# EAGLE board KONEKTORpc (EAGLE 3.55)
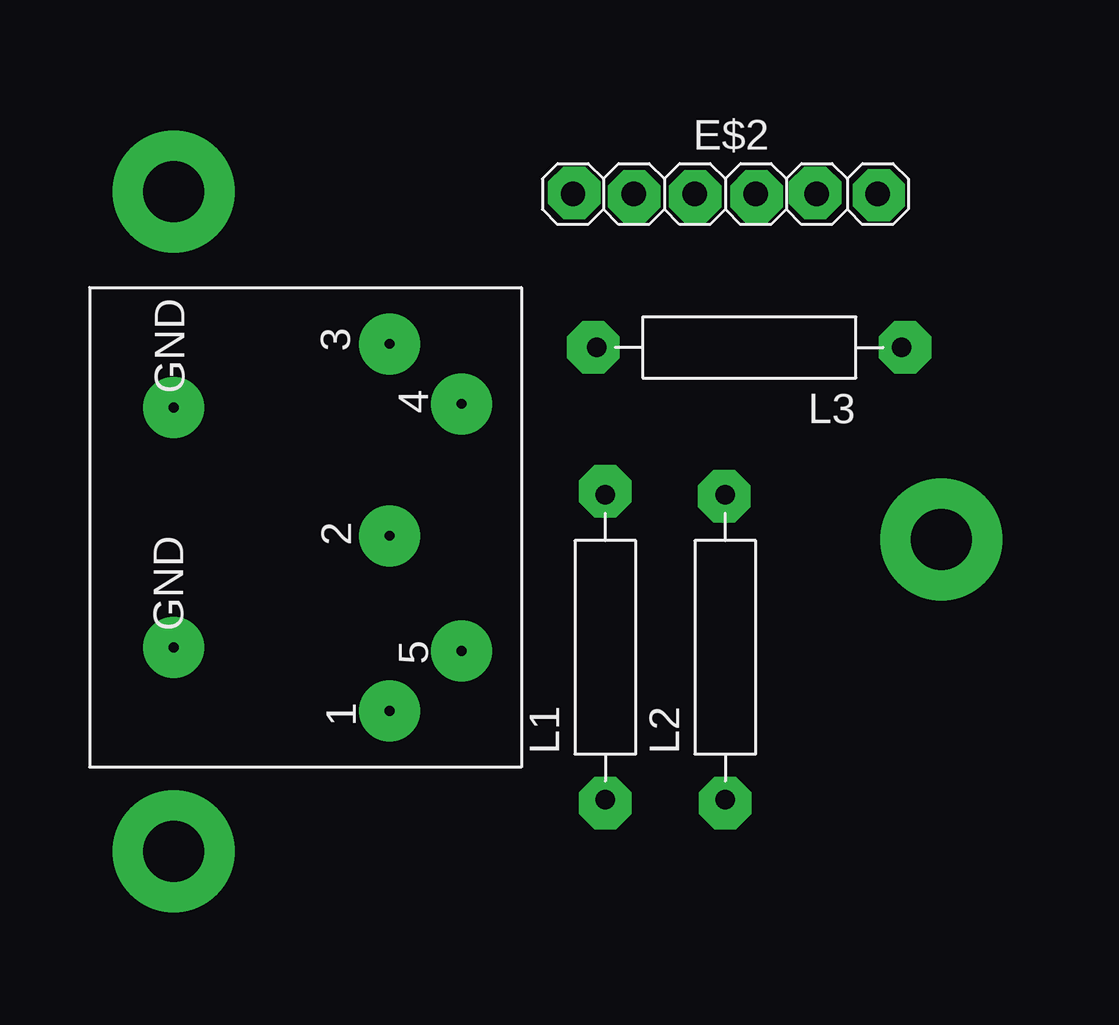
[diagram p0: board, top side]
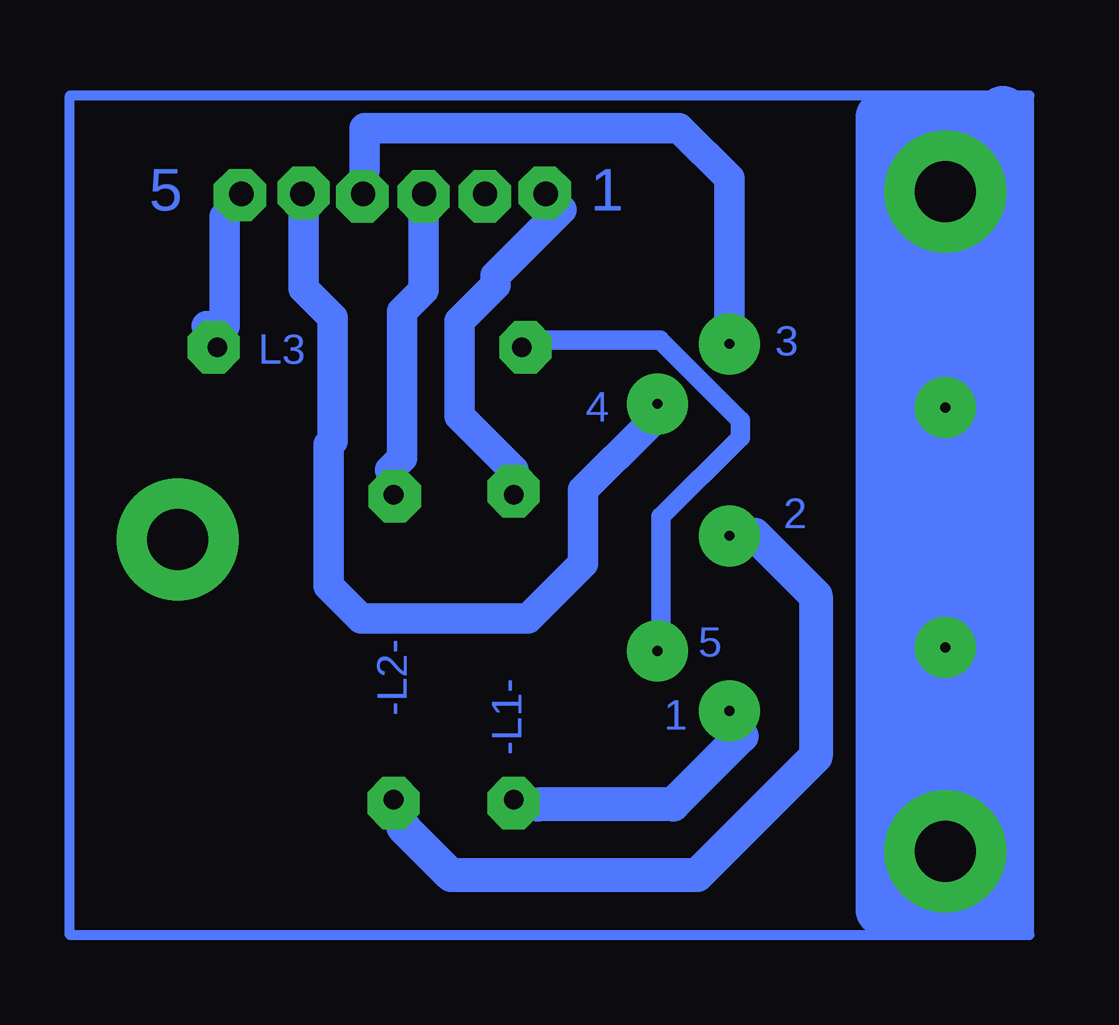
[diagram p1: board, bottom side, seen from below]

No outline drawn. Coordinates in mm, seen from the top.
Copper layers used: Bottom

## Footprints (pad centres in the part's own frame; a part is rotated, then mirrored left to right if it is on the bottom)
N 5 C = drill 0.406 pad 2.54 round:  5,3.5;  15,3.5;  10.35,12.5;  2.35,12.5;  17.65,12.5;  15.15,15.5;  4.85,15.5
06 = drill 1.016 pad 1.575 octagon:  -6.35,0;  -3.81,0;  -1.27,0;  1.27,0;  3.81,0;  6.35,0
12,5 = drill 0.813 pad 1.397 octagon:  -6.35,0;  6.35,0

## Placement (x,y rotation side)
E$1  [N 5 C]  0,27 270 top
E$2  K1  [06]  26.5,30.9 0 top
L1  [12,5]  21.5,12 90 top
L2  [12,5]  26.5,12 90 top
L3  [12,5]  27.5,24.5 180 top

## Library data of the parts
E$1 = hacesoft
E$2 = PINHEAD
L1-L3 = PASSIVE

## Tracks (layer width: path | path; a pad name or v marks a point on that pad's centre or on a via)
K1
  Bottom 1.27: 12.5,25.55 12.5,31.55 14.6,33.65 27.7,33.65 27.7,31.9
K2
  Bottom 0.406: 0,0 0,35 40,35 40,0 0,0
S$2  (via drill 2.54 pad 5.08)
  other vias: 3.5,3.5
S$3  (via drill 2.54 pad 5.08)
  other vias: 3.5,31
S$4  (via drill 2.54 pad 5.08)
  other vias: 35.5,16.5
S$5
  Bottom 1.27: 34.3,25.4 33.55,25.4 33.55,29.95
S$6  (via drill 0.25 pad 2.18)
  other vias: 26.45,18.3
S$7  (via drill 0.25 pad 2.18)
  other vias: 20.2,30.95
S$8  (via drill 0.25 pad 2.18)
  other vias: 22.7,30.8
S$10  (via drill 0.25 pad 2.18)
  other vias: 27.8,30.8
S$11  (via drill 0.25 pad 2.18)
  Bottom 1.27: 15.9,21.25 18.6,18.55 18.6,15.5 20.9,13.2 27.85,13.2 29.2,14.55 29.2,20.45 29.05,20.6 29.05,25.75 30.25,26.95 30.25,29.65 30.25,30.05
  other vias: 30.25,30.95
S$12  (via drill 0.25 pad 2.18)
  other vias: 34,24.5
S$13  (via drill 0.25 pad 2.18)
  Bottom 0.813: 20.25,24.8 15.4,24.8 12.05,21.45 12.05,20.75 15.35,17.45 15.35,12.65
  other vias: 21,24.5
S$14  (via drill 0.25 pad 2.18)
  Bottom 1.27: 21.5,19.4 23.75,21.65 23.75,25.6 22.25,27.1 22.25,27.5 19.5,30.25
  other vias: 21.5,18.5
S$16  (via drill 0.25 pad 2.18)
  other vias: 26.5,5.5
S$17  (via drill 0.25 pad 2.18)
  Bottom 1.422: 12,8.3 14.85,5.45 20.5,5.45
  other vias: 21.5,5.5
S$18  (via drill 0.25 pad 2.18)
  other vias: 32.9,30.85
S$19  (via drill 0.25 pad 2.18)
  Bottom 1.27: 26.65,19.4 26.15,19.9 26.15,26 25.25,26.9 25.25,29.65 25.25,29.8
  other vias: 25.25,30.8
S$24
  Bottom 1.422: 11.45,16.7 8.9,14.15 8.9,7.45 13.85,2.5 24.1,2.5 26.1,4.5 26.1,4.55
S$27
  Bottom 2.184: 1.1,34.3 0.95,34.15 0.95,0.95 1.05,1.05 6.15,1.05 6.15,34.1 5.9,33.85 2.05,33.85
S$28
  Bottom 2.184: 1.2,28.95 1.6,28.55 5.15,28.55 5.15,5.6 4.65,6.1 2.3,6.1 2.3,10.55 3.35,10.55 3.4,10.5 3.4,7.6 2.05,8.95 2.05,11.6 2.15,11.7 2.15,27 2.35,26.8 3.4,26.8 3.6,26.6 3.6,23.7
S$29
  Bottom 2.184: 3.55,20.8 3.4,20.65 3.4,13.6

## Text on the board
Bottom: 1 | 5 | 3 | L3 | 4 | 2 | 5 | -L2- | 1 | -L1-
